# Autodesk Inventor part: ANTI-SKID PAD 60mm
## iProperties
Created: 2007-03
Part Number: ANTI-SKID PAD 60mm
Material: Rubber
Document SubType Name: Modeling
Designer: Andy Moles
Density: 0.93 g/cm^3
Author: Andy Moles
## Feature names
1. Extrusion1
2. Extrusion2
3. Fillet1
